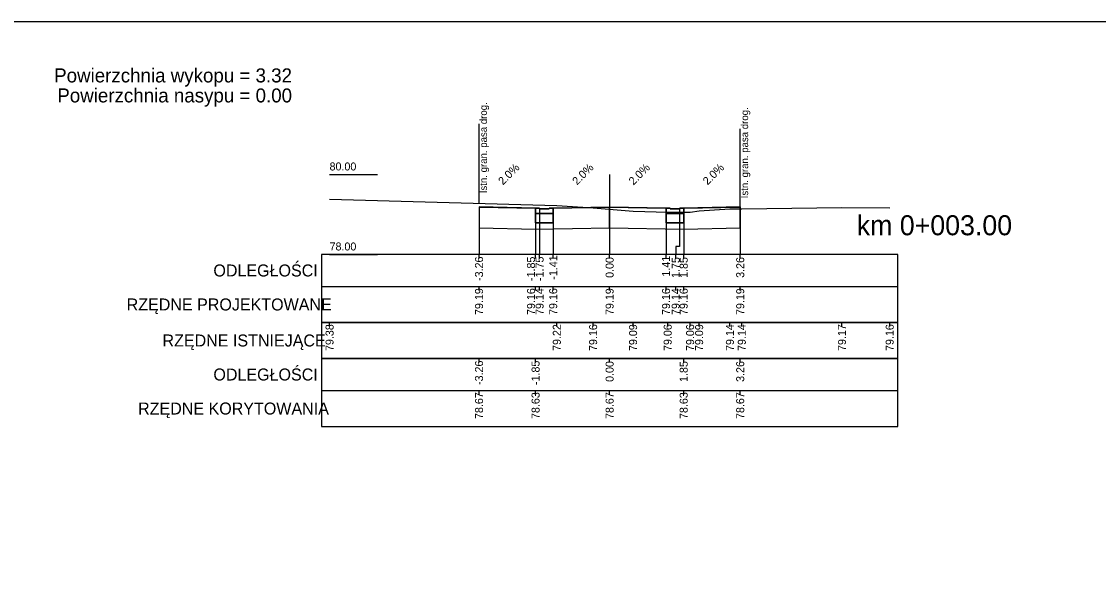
# Model space of a CAD drawing. Extents: x 7492871 to 7493499, y 5802964 to 5802992.
# Drawn here: x 7492987.07 to 7493013.99, y 5802978.41 to 5802992.28 of the extents above; entities that cross this region are included whole.
import ezdxf

# ---------------------------------------------------------------- set-up
doc = ezdxf.new("R2010")
doc.units = 0
for name, color, linetype in [('_wydruk', 7, 'Continuous'), ('d_pop_nasyp_opis', 7, 'Continuous'), ('d_pop_wykop_opis', 7, 'Continuous'), ('opisy_ramki_pop', 7, 'Continuous'), ('pop_comp_kostka', 7, 'Continuous'), ('pop_comp_lawa', 7, 'Continuous'), ('pop_comp_scieralna', 7, 'Continuous'), ('pop_granica_istn', 7, 'Continuous'), ('pop_opis', 7, 'Continuous'), ('pop_os', 7, 'Continuous'), ('pop_pikietaz', 7, 'Continuous'), ('pop_teren', 7, 'Continuous')]:
    doc.layers.add(name, color=color, linetype=linetype)

msp = doc.modelspace()

# ---------------------------------------------------------------- linework, layer by layer
msp.add_lwpolyline([(7492998.504, 5802987.646), (7492998.519, 5802987.645), (7492999.917, 5802987.617), (7493000.016, 5802987.617), (7493000.017, 5802987.617), (7493000.018, 5802987.597), (7493000.254, 5802987.597), (7493000.257, 5802987.597), (7493000.258, 5802987.617), (7493000.357, 5802987.617), (7493000.358, 5802987.617), (7493001.753, 5802987.645), (7493001.768, 5802987.645), (7493003.163, 5802987.618), (7493003.178, 5802987.617), (7493003.277, 5802987.617), (7493003.278, 5802987.617), (7493003.279, 5802987.597), (7493003.515, 5802987.597), (7493003.518, 5802987.597), (7493003.519, 5802987.617), (7493003.618, 5802987.617), (7493003.619, 5802987.617), (7493005.017, 5802987.645), (7493005.032, 5802987.646)])
at = {"layer": '_wydruk'}
msp.add_lwpolyline([(7492871.369, 5802992.281), (7493499.283, 5802992.281), (7493499.283, 5802963.881), (7492871.369, 5802963.881)], close=True, dxfattribs=at)
at = {"layer": 'opisy_ramki_pop'}
for points in [[(7492998.504, 5802987.125), (7492998.504, 5802986.659), (7492998.504, 5802986.659), (7492998.504, 5802986.459)], [(7492999.917, 5802987.088), (7492999.917, 5802986.659), (7492999.917, 5802986.659), (7492999.917, 5802986.459)], [(7493001.768, 5802987.125), (7493001.768, 5802986.659), (7493001.768, 5802986.659), (7493001.768, 5802986.459)], [(7493003.619, 5802987.088), (7493003.619, 5802986.659), (7493003.619, 5802986.659), (7493003.619, 5802986.459)], [(7493005.032, 5802987.125), (7493005.032, 5802986.659), (7493005.032, 5802986.659), (7493005.032, 5802986.459)]]:
    msp.add_lwpolyline(points, dxfattribs=at)
at = {"layer": 'pop_comp_kostka'}
for p, q in [((7493000.017, 5802987.617), (7492999.917, 5802987.617)), ((7492999.917, 5802987.617), (7492999.917, 5802987.487)), ((7492999.917, 5802987.487), (7493000.358, 5802987.487)), ((7493000.018, 5802987.597), (7493000.017, 5802987.617)), ((7493000.257, 5802987.597), (7493000.018, 5802987.597)), ((7493000.258, 5802987.617), (7493000.257, 5802987.597)), ((7493000.358, 5802987.617), (7493000.258, 5802987.617)), ((7493000.358, 5802987.487), (7493000.358, 5802987.617)), ((7493003.278, 5802987.617), (7493003.178, 5802987.617)), ((7493003.178, 5802987.617), (7493003.178, 5802987.487)), ((7493003.178, 5802987.487), (7493003.619, 5802987.487)), ((7493003.279, 5802987.597), (7493003.278, 5802987.617)), ((7493003.518, 5802987.597), (7493003.279, 5802987.597)), ((7493003.519, 5802987.617), (7493003.518, 5802987.597)), ((7493003.619, 5802987.617), (7493003.519, 5802987.617)), ((7493003.619, 5802987.487), (7493003.619, 5802987.617))]:
    msp.add_line(p, q, dxfattribs=at)
at = {"layer": 'pop_comp_lawa'}
for p, q in [((7493000.358, 5802987.487), (7492999.917, 5802987.487)), ((7492999.917, 5802987.487), (7492999.917, 5802987.247)), ((7493000.358, 5802987.247), (7493000.358, 5802987.487)), ((7493003.619, 5802987.487), (7493003.178, 5802987.487)), ((7493003.178, 5802987.487), (7493003.178, 5802987.247)), ((7493003.619, 5802987.247), (7493003.619, 5802987.487)), ((7492999.917, 5802987.247), (7493000.358, 5802987.247)), ((7493003.178, 5802987.247), (7493003.619, 5802987.247))]:
    msp.add_line(p, q, dxfattribs=at)
at = {"layer": 'pop_comp_scieralna'}
for p, q in [((7492999.917, 5802987.617), (7492998.504, 5802987.646)), ((7492998.504, 5802987.646), (7492998.504, 5802987.125)), ((7492999.917, 5802987.247), (7492999.917, 5802987.617)), ((7493001.768, 5802987.645), (7493000.358, 5802987.617)), ((7493000.358, 5802987.617), (7493000.358, 5802987.247)), ((7493001.768, 5802987.125), (7493001.768, 5802987.645)), ((7493003.178, 5802987.617), (7493001.768, 5802987.645)), ((7493001.768, 5802987.645), (7493001.768, 5802987.125)), ((7493003.178, 5802987.247), (7493003.178, 5802987.617)), ((7493005.032, 5802987.646), (7493003.619, 5802987.617)), ((7493003.619, 5802987.617), (7493003.619, 5802987.247)), ((7493005.032, 5802987.125), (7493005.032, 5802987.646)), ((7493000.358, 5802987.247), (7492999.917, 5802987.247)), ((7493003.619, 5802987.247), (7493003.178, 5802987.247)), ((7492998.504, 5802987.125), (7492999.917, 5802987.088)), ((7492999.917, 5802987.088), (7493001.768, 5802987.125)), ((7493001.768, 5802987.125), (7493003.619, 5802987.088)), ((7493003.619, 5802987.088), (7493005.032, 5802987.125))]:
    msp.add_line(p, q, dxfattribs=at)
at = {"layer": 'pop_granica_istn'}
for p, q in [((7492998.504, 5802988.228), (7492998.504, 5802989.728)), ((7493005.032, 5802988.102), (7493005.032, 5802989.602)), ((7492998.504, 5802987.728), (7492998.504, 5802988.228)), ((7493005.032, 5802987.602), (7493005.032, 5802988.102))]:
    msp.add_line(p, q, dxfattribs=at)
at = {"layer": 'pop_opis'}
for p, q in [((7492994.768, 5802988.459), (7492995.968, 5802988.459)), ((7492994.568, 5802986.459), (7492994.568, 5802984.759)), ((7492994.568, 5802986.459), (7492994.568, 5802984.759)), ((7492994.568, 5802986.459), (7492994.568, 5802984.759)), ((7492994.568, 5802986.459), (7492994.568, 5802984.759)), ((7492994.768, 5802986.459), (7492995.968, 5802986.459)), ((7492998.504, 5802986.359), (7492998.504, 5802986.459)), ((7492999.917, 5802986.359), (7492999.917, 5802986.459)), ((7493000.018, 5802986.359), (7493000.018, 5802986.459)), ((7493000.358, 5802986.359), (7493000.358, 5802986.459)), ((7493001.768, 5802986.359), (7493001.768, 5802986.459)), ((7493003.178, 5802986.359), (7493003.178, 5802986.459)), ((7493003.419, 5802986.359), (7493003.419, 5802986.459)), ((7493003.619, 5802986.359), (7493003.619, 5802986.459)), ((7493005.032, 5802986.359), (7493005.032, 5802986.459)), ((7492994.568, 5802985.659), (7493008.968, 5802985.659)), ((7492994.568, 5802985.659), (7493008.968, 5802985.659)), ((7492994.568, 5802985.659), (7493008.968, 5802985.659)), ((7492994.568, 5802985.659), (7493008.968, 5802985.659)), ((7492998.504, 5802985.559), (7492998.504, 5802985.659)), ((7492999.917, 5802985.559), (7492999.917, 5802985.659)), ((7493000.018, 5802985.559), (7493000.018, 5802985.659)), ((7493000.358, 5802985.559), (7493000.358, 5802985.659)), ((7493001.768, 5802985.559), (7493001.768, 5802985.659)), ((7493003.178, 5802985.559), (7493003.178, 5802985.659)), ((7493003.419, 5802985.559), (7493003.419, 5802985.659)), ((7493003.619, 5802985.559), (7493003.619, 5802985.659)), ((7493005.032, 5802985.559), (7493005.032, 5802985.659)), ((7492994.568, 5802984.759), (7492994.568, 5802983.859)), ((7492994.768, 5802984.659), (7492994.768, 5802984.759)), ((7493000.448, 5802984.659), (7493000.448, 5802984.759)), ((7493001.355, 5802984.659), (7493001.355, 5802984.759)), ((7493002.354, 5802984.659), (7493002.354, 5802984.759)), ((7493003.219, 5802984.659), (7493003.219, 5802984.759)), ((7493003.78, 5802984.659), (7493003.78, 5802984.759)), ((7493004.005, 5802984.659), (7493004.005, 5802984.759)), ((7493004.775, 5802984.659), (7493004.775, 5802984.759)), ((7493005.072, 5802984.659), (7493005.072, 5802984.759)), ((7493007.575, 5802984.659), (7493007.575, 5802984.759)), ((7493008.768, 5802984.659), (7493008.768, 5802984.759)), ((7492994.568, 5802983.859), (7492994.568, 5802982.159)), ((7492998.504, 5802983.759), (7492998.504, 5802983.859)), ((7492999.917, 5802983.759), (7492999.917, 5802983.859)), ((7493001.768, 5802983.759), (7493001.768, 5802983.859)), ((7493003.619, 5802983.759), (7493003.619, 5802983.859)), ((7493005.032, 5802983.759), (7493005.032, 5802983.859)), ((7492994.568, 5802983.059), (7493008.968, 5802983.059)), ((7492998.504, 5802982.959), (7492998.504, 5802983.059)), ((7492999.917, 5802982.959), (7492999.917, 5802983.059)), ((7493001.768, 5802982.959), (7493001.768, 5802983.059)), ((7493003.619, 5802982.959), (7493003.619, 5802983.059)), ((7493005.032, 5802982.959), (7493005.032, 5802983.059))]:
    msp.add_line(p, q, dxfattribs=at)
for points in [[(7492998.504, 5802987.646), (7492998.504, 5802986.659), (7492998.504, 5802986.659), (7492998.504, 5802986.459)], [(7492999.917, 5802987.617), (7492999.917, 5802986.659), (7492999.917, 5802986.659), (7492999.917, 5802986.459)], [(7493000.018, 5802987.597), (7493000.018, 5802986.659), (7493000.018, 5802986.659), (7493000.018, 5802986.459)], [(7493000.358, 5802987.617), (7493000.358, 5802986.659), (7493000.358, 5802986.659), (7493000.358, 5802986.459)], [(7493001.768, 5802987.645), (7493001.768, 5802986.659), (7493001.768, 5802986.659), (7493001.768, 5802986.459)], [(7493003.178, 5802987.617), (7493003.178, 5802986.659), (7493003.178, 5802986.659), (7493003.178, 5802986.459)], [(7493003.518, 5802987.597), (7493003.518, 5802986.659), (7493003.419, 5802986.659), (7493003.419, 5802986.459)], [(7493003.619, 5802987.617), (7493003.619, 5802986.659), (7493003.619, 5802986.659), (7493003.619, 5802986.459)], [(7493005.032, 5802987.646), (7493005.032, 5802986.659), (7493005.032, 5802986.659), (7493005.032, 5802986.459)]]:
    msp.add_lwpolyline(points, dxfattribs=at)
for points in [[(7492994.568, 5802986.459), (7492994.568, 5802984.759), (7493008.968, 5802984.759), (7493008.968, 5802986.459)], [(7492994.568, 5802986.459), (7492994.568, 5802984.759), (7493008.968, 5802984.759), (7493008.968, 5802986.459)], [(7492994.568, 5802986.459), (7492994.568, 5802984.759), (7493008.968, 5802984.759), (7493008.968, 5802986.459)], [(7492994.568, 5802986.459), (7492994.568, 5802984.759), (7493008.968, 5802984.759), (7493008.968, 5802986.459)], [(7492994.568, 5802984.759), (7492994.568, 5802983.859), (7493008.968, 5802983.859), (7493008.968, 5802984.759)], [(7492994.568, 5802983.859), (7492994.568, 5802982.159), (7493008.968, 5802982.159), (7493008.968, 5802983.859)]]:
    msp.add_lwpolyline(points, close=True, dxfattribs=at)
at = {"layer": 'pop_os'}
msp.add_line((7493001.768, 5802988.459), (7493001.768, 5802986.459), dxfattribs=at)
at = {"layer": 'pop_teren'}
msp.add_lwpolyline([(7492994.768, 5802987.84), (7493000.448, 5802987.68), (7493001.355, 5802987.621), (7493002.354, 5802987.544), (7493003.219, 5802987.518), (7493003.78, 5802987.519), (7493004.005, 5802987.552), (7493004.775, 5802987.602), (7493005.072, 5802987.602), (7493007.575, 5802987.633), (7493008.768, 5802987.622)], dxfattribs=at)

# ---------------------------------------------------------------- texts
at = {"layer": 'd_pop_nasyp_opis'}
msp.add_text('Powierzchnia nasypu = 0.00', height=0.35, dxfattribs=at).set_placement((7492987.963, 5802990.259))
at = {"layer": 'd_pop_wykop_opis'}
msp.add_text('Powierzchnia wykopu = 3.32', height=0.35, dxfattribs=at).set_placement((7492987.884, 5802990.759))
at = {"layer": 'pop_granica_istn'}
for p in [(7492998.702, 5802987.989), (7493005.23, 5802987.863)]:
    msp.add_text('Istn. gran. pasa drog.', height=0.18, rotation=90, dxfattribs=at).set_placement(p)
at = {"layer": 'pop_opis'}
for s, height, p in [('80.00', 0.2, (7492994.768, 5802988.559)), ('78.00', 0.2, (7492994.768, 5802986.559)), ('ODLEGŁOŚCI', 0.3, (7492991.864, 5802985.909)), ('ODLEGŁOŚCI', 0.3, (7492991.864, 5802985.909)), ('ODLEGŁOŚCI', 0.3, (7492991.864, 5802985.909)), ('ODLEGŁOŚCI', 0.3, (7492991.864, 5802985.909)), ('RZĘDNE PROJEKTOWANE', 0.3, (7492989.696, 5802985.059)), ('RZĘDNE PROJEKTOWANE', 0.3, (7492989.696, 5802985.059)), ('RZĘDNE PROJEKTOWANE', 0.3, (7492989.696, 5802985.059)), ('RZĘDNE PROJEKTOWANE', 0.3, (7492989.696, 5802985.059)), ('RZĘDNE ISTNIEJĄCE', 0.3, (7492990.592, 5802984.159)), ('ODLEGŁOŚCI', 0.3, (7492991.864, 5802983.309)), ('RZĘDNE KORYTOWANIA', 0.3, (7492989.982, 5802982.459))]:
    msp.add_text(s, height=height, dxfattribs=at).set_placement(p)
for s, rotation, p in [('2.0%', 45, (7492999.102, 5802988.181)), ('2.0%', 45, (7493000.954, 5802988.181)), ('2.0%', 45, (7493002.364, 5802988.181)), ('2.0%', 45, (7493004.217, 5802988.181)), ('-3.26', 90, (7492998.604, 5802985.798)), ('-1.85', 90, (7492999.903, 5802985.796)), ('-1.75', 90, (7493000.118, 5802985.796)), ('-1.41', 90, (7493000.458, 5802985.829)), ('0.00', 90, (7493001.868, 5802985.874)), ('1.41', 90, (7493003.278, 5802985.905)), ('1.75', 90, (7493003.519, 5802985.873)), ('1.85', 90, (7493003.719, 5802985.873)), ('3.26', 90, (7493005.132, 5802985.874)), ('79.19', 90, (7492998.604, 5802984.946)), ('79.16', 90, (7492999.903, 5802984.947)), ('79.14', 90, (7493000.118, 5802984.947)), ('79.16', 90, (7493000.458, 5802984.947)), ('79.19', 90, (7493001.868, 5802984.946)), ('79.16', 90, (7493003.278, 5802984.947)), ('79.14', 90, (7493003.519, 5802984.947)), ('79.16', 90, (7493003.719, 5802984.947)), ('79.19', 90, (7493005.132, 5802984.946)), ('79.38', 90, (7492994.868, 5802984.046)), ('79.22', 90, (7493000.548, 5802984.048)), ('79.16', 90, (7493001.455, 5802984.047)), ('79.09', 90, (7493002.454, 5802984.046)), ('79.06', 90, (7493003.319, 5802984.047)), ('79.06', 90, (7493003.88, 5802984.047)), ('79.09', 90, (7493004.105, 5802984.046)), ('79.14', 90, (7493004.875, 5802984.047)), ('79.14', 90, (7493005.172, 5802984.047)), ('79.17', 90, (7493007.675, 5802984.047)), ('79.16', 90, (7493008.868, 5802984.047)), ('-3.26', 90, (7492998.604, 5802983.198)), ('-1.85', 90, (7493000.017, 5802983.196)), ('0.00', 90, (7493001.868, 5802983.274)), ('1.85', 90, (7493003.719, 5802983.273)), ('3.26', 90, (7493005.132, 5802983.274)), ('78.67', 90, (7492998.604, 5802982.347)), ('78.63', 90, (7493000.017, 5802982.347)), ('78.67', 90, (7493001.868, 5802982.347)), ('78.63', 90, (7493003.719, 5802982.347)), ('78.67', 90, (7493005.132, 5802982.347))]:
    msp.add_text(s, height=0.2, rotation=rotation, dxfattribs=at).set_placement(p)
at = {"layer": 'pop_pikietaz'}
msp.add_text('km 0+003.00', height=0.5, dxfattribs=at).set_placement((7493007.944, 5802986.939))

doc.saveas('drawing.dxf')
